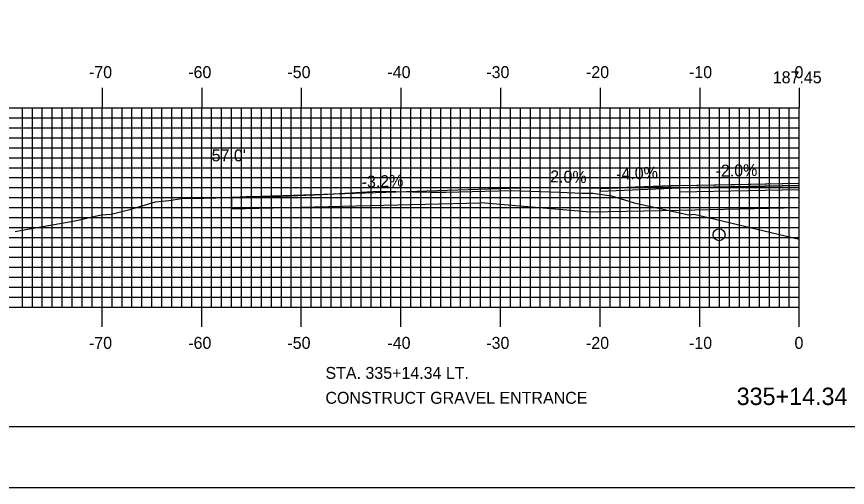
# Model space of a CAD drawing. Extents: x 1823573 to 1823916, y 442591 to 442811.
# Drawn here: x 1823659.7 to 1823743.1, y 442590.5 to 442637.8 of the extents above; entities that cross this region are included whole.
import ezdxf

# ---------------------------------------------------------------- set-up
doc = ezdxf.new("R2010")
doc.units = 0
for name, color, linetype in [('ANNOTATION', 7, 'Continuous'), ('BORDER', 7, 'Continuous'), ('D_Roadway_Centerline', 7, 'Continuous'), ('D_Roadway_Centerline_Text', 7, 'Continuous'), ('D_Roadway_Edge_Shoulder', 7, 'Continuous'), ('D_Roadway_Edge_TW', 7, 'Continuous'), ('D_Roadway_Pavement', 7, 'Continuous'), ('D_Roadway_SubGrade', 7, 'Continuous'), ('D_Text_Standard', 7, 'Continuous'), ('H_V ANNOTATION', 7, 'Continuous'), ('MAJOR', 7, 'Continuous'), ('MINOR', 7, 'Continuous'), ('PLOT BOUNDARY', 7, 'Continuous'), ('S_Drainage_Invert', 7, 'Continuous'), ('S_Roadway_Centerline', 7, 'Continuous')]:
    doc.layers.add(name, color=color, linetype=linetype)

msp = doc.modelspace()

# ---------------------------------------------------------------- linework, layer by layer
at = {"layer": 'BORDER'}
msp.add_lwpolyline([(1823588.709, 442596.665), (1823908.709, 442596.665), (1823908.709, 442806.665), (1823588.709, 442806.665)], close=True, dxfattribs=at)
at = {"layer": 'D_Roadway_Centerline'}
for p, q in [((1823681.309, 442619.681), (1823681.309, 442618.514)), ((1823681.309, 442618.514), (1823706.325, 442619.123))]:
    msp.add_line(p, q, dxfattribs=at)
for points in [[(1823718.309, 442620.556), (1823712.309, 442620.676), (1823681.309, 442619.681)], [(1823718.309, 442620.556), (1823721.974, 442620.703), (1823726.309, 442620.876), (1823731.806, 442620.986), (1823738.309, 442621.116)], [(1823718.325, 442618.216), (1823717.325, 442618.196), (1823706.325, 442619.123)]]:
    msp.add_lwpolyline(points, dxfattribs=at)
at = {"layer": 'D_Roadway_Edge_Shoulder'}
msp.add_lwpolyline([(1823726.309, 442620.876), (1823718.309, 442620.556), (1823718.309, 442620.306), (1823726.309, 442620.626)], close=True, dxfattribs=at)
at = {"layer": 'D_Roadway_Edge_TW'}
msp.add_lwpolyline([(1823738.309, 442620.866), (1823726.309, 442620.626), (1823726.309, 442620.876), (1823738.309, 442621.116)], dxfattribs=at)
at = {"layer": 'D_Roadway_Pavement'}
msp.add_lwpolyline([(1823738.309, 442620.449), (1823726.309, 442620.209), (1823726.309, 442620.626), (1823738.309, 442620.866)], dxfattribs=at)
at = {"layer": 'D_Roadway_SubGrade'}
for points in [[(1823718.309, 442620.556), (1823718.309, 442620.306), (1823726.309, 442620.626), (1823738.309, 442620.866)], [(1823738.309, 442618.616), (1823726.309, 442618.376), (1823717.325, 442618.196)]]:
    msp.add_lwpolyline(points, dxfattribs=at)
at = {"layer": 'MAJOR'}
for p, q in [((1823668.309, 442630.669), (1823668.309, 442628.665)), ((1823678.309, 442630.669), (1823678.309, 442628.665)), ((1823688.309, 442630.669), (1823688.309, 442628.665)), ((1823698.309, 442630.669), (1823698.309, 442628.665)), ((1823708.309, 442630.669), (1823708.309, 442628.665)), ((1823718.309, 442630.669), (1823718.309, 442628.665)), ((1823728.309, 442630.669), (1823728.309, 442628.665)), ((1823738.309, 442630.669), (1823738.309, 442628.665)), ((1823598.309, 442628.665), (1823738.309, 442628.665)), ((1823598.309, 442628.665), (1823738.309, 442628.665)), ((1823668.309, 442608.665), (1823668.309, 442628.665)), ((1823678.309, 442608.665), (1823678.309, 442628.665)), ((1823688.309, 442608.665), (1823688.309, 442628.665)), ((1823698.309, 442608.665), (1823698.309, 442628.665)), ((1823708.309, 442608.665), (1823708.309, 442628.665)), ((1823718.309, 442608.665), (1823718.309, 442628.665)), ((1823728.309, 442608.665), (1823728.309, 442628.665)), ((1823738.309, 442608.665), (1823738.309, 442628.665)), ((1823598.309, 442623.665), (1823738.309, 442623.665)), ((1823598.309, 442618.665), (1823738.309, 442618.665)), ((1823598.309, 442613.665), (1823738.309, 442613.665)), ((1823598.309, 442608.665), (1823738.309, 442608.665)), ((1823598.309, 442608.665), (1823738.309, 442608.665)), ((1823668.309, 442606.661), (1823668.309, 442608.665)), ((1823678.309, 442606.661), (1823678.309, 442608.665)), ((1823688.309, 442606.661), (1823688.309, 442608.665)), ((1823698.309, 442606.661), (1823698.309, 442608.665)), ((1823708.309, 442606.661), (1823708.309, 442608.665)), ((1823718.309, 442606.661), (1823718.309, 442608.665)), ((1823728.309, 442606.661), (1823728.309, 442608.665)), ((1823738.309, 442606.661), (1823738.309, 442608.665))]:
    msp.add_line(p, q, dxfattribs=at)
at = {"layer": 'MINOR'}
for p, q in [((1823660.309, 442608.665), (1823660.309, 442628.665)), ((1823661.309, 442608.665), (1823661.309, 442628.665)), ((1823662.309, 442608.665), (1823662.309, 442628.665)), ((1823663.309, 442608.665), (1823663.309, 442628.665)), ((1823664.309, 442608.665), (1823664.309, 442628.665)), ((1823665.309, 442608.665), (1823665.309, 442628.665)), ((1823666.309, 442608.665), (1823666.309, 442628.665)), ((1823667.309, 442608.665), (1823667.309, 442628.665)), ((1823669.309, 442608.665), (1823669.309, 442628.665)), ((1823670.309, 442608.665), (1823670.309, 442628.665)), ((1823671.309, 442608.665), (1823671.309, 442628.665)), ((1823672.309, 442608.665), (1823672.309, 442628.665)), ((1823673.309, 442608.665), (1823673.309, 442628.665)), ((1823674.309, 442608.665), (1823674.309, 442628.665)), ((1823675.309, 442608.665), (1823675.309, 442628.665)), ((1823676.309, 442608.665), (1823676.309, 442628.665)), ((1823677.309, 442608.665), (1823677.309, 442628.665)), ((1823679.309, 442608.665), (1823679.309, 442628.665)), ((1823680.309, 442608.665), (1823680.309, 442628.665)), ((1823681.309, 442608.665), (1823681.309, 442628.665)), ((1823682.309, 442608.665), (1823682.309, 442628.665)), ((1823683.309, 442608.665), (1823683.309, 442628.665)), ((1823684.309, 442608.665), (1823684.309, 442628.665)), ((1823685.309, 442608.665), (1823685.309, 442628.665)), ((1823686.309, 442608.665), (1823686.309, 442628.665)), ((1823687.309, 442608.665), (1823687.309, 442628.665)), ((1823689.309, 442608.665), (1823689.309, 442628.665)), ((1823690.309, 442608.665), (1823690.309, 442628.665)), ((1823691.309, 442608.665), (1823691.309, 442628.665)), ((1823692.309, 442608.665), (1823692.309, 442628.665)), ((1823693.309, 442608.665), (1823693.309, 442628.665)), ((1823694.309, 442608.665), (1823694.309, 442628.665)), ((1823695.309, 442608.665), (1823695.309, 442628.665)), ((1823696.309, 442608.665), (1823696.309, 442628.665)), ((1823697.309, 442608.665), (1823697.309, 442628.665)), ((1823699.309, 442608.665), (1823699.309, 442628.665)), ((1823700.309, 442608.665), (1823700.309, 442628.665)), ((1823701.309, 442608.665), (1823701.309, 442628.665)), ((1823702.309, 442608.665), (1823702.309, 442628.665)), ((1823703.309, 442608.665), (1823703.309, 442628.665)), ((1823704.309, 442608.665), (1823704.309, 442628.665)), ((1823705.309, 442608.665), (1823705.309, 442628.665)), ((1823706.309, 442608.665), (1823706.309, 442628.665)), ((1823707.309, 442608.665), (1823707.309, 442628.665)), ((1823709.309, 442608.665), (1823709.309, 442628.665)), ((1823710.309, 442608.665), (1823710.309, 442628.665)), ((1823711.309, 442608.665), (1823711.309, 442628.665)), ((1823712.309, 442608.665), (1823712.309, 442628.665)), ((1823713.309, 442608.665), (1823713.309, 442628.665)), ((1823714.309, 442608.665), (1823714.309, 442628.665)), ((1823715.309, 442608.665), (1823715.309, 442628.665)), ((1823716.309, 442608.665), (1823716.309, 442628.665)), ((1823717.309, 442608.665), (1823717.309, 442628.665)), ((1823719.309, 442608.665), (1823719.309, 442628.665)), ((1823720.309, 442608.665), (1823720.309, 442628.665)), ((1823721.309, 442608.665), (1823721.309, 442628.665)), ((1823722.309, 442608.665), (1823722.309, 442628.665)), ((1823723.309, 442608.665), (1823723.309, 442628.665)), ((1823724.309, 442608.665), (1823724.309, 442628.665)), ((1823725.309, 442608.665), (1823725.309, 442628.665)), ((1823726.309, 442608.665), (1823726.309, 442628.665)), ((1823727.309, 442608.665), (1823727.309, 442628.665)), ((1823729.309, 442608.665), (1823729.309, 442628.665)), ((1823730.309, 442608.665), (1823730.309, 442628.665)), ((1823731.309, 442608.665), (1823731.309, 442628.665)), ((1823732.309, 442608.665), (1823732.309, 442628.665)), ((1823733.309, 442608.665), (1823733.309, 442628.665)), ((1823734.309, 442608.665), (1823734.309, 442628.665)), ((1823735.309, 442608.665), (1823735.309, 442628.665)), ((1823736.309, 442608.665), (1823736.309, 442628.665)), ((1823737.309, 442608.665), (1823737.309, 442628.665)), ((1823598.309, 442627.665), (1823738.309, 442627.665)), ((1823598.309, 442626.665), (1823738.309, 442626.665)), ((1823598.309, 442625.665), (1823738.309, 442625.665)), ((1823598.309, 442624.665), (1823738.309, 442624.665)), ((1823598.309, 442622.665), (1823738.309, 442622.665)), ((1823598.309, 442621.665), (1823738.309, 442621.665)), ((1823598.309, 442620.665), (1823738.309, 442620.665)), ((1823598.309, 442619.665), (1823738.309, 442619.665)), ((1823598.309, 442617.665), (1823738.309, 442617.665)), ((1823598.309, 442616.665), (1823738.309, 442616.665)), ((1823598.309, 442615.665), (1823738.309, 442615.665)), ((1823598.309, 442614.665), (1823738.309, 442614.665)), ((1823598.309, 442612.665), (1823738.309, 442612.665)), ((1823598.309, 442611.665), (1823738.309, 442611.665)), ((1823598.309, 442610.665), (1823738.309, 442610.665)), ((1823598.309, 442609.665), (1823738.309, 442609.665))]:
    msp.add_line(p, q, dxfattribs=at)
at = {"layer": 'PLOT BOUNDARY'}
msp.add_lwpolyline([(1823572.522, 442590.547), (1823912.522, 442590.547), (1823912.522, 442810.547), (1823572.522, 442810.547)], close=True, dxfattribs=at)
at = {"layer": 'S_Drainage_Invert'}
msp.add_circle((1823730.252, 442615.927), 0.6, dxfattribs=at)
at = {"layer": 'S_Roadway_Centerline'}
msp.add_lwpolyline([(1823659.583, 442616.261), (1823660.287, 442616.401), (1823665.589, 442617.335), (1823668.214, 442617.92), (1823669.21, 442617.983), (1823671.111, 442618.449), (1823673.687, 442619.241), (1823675.014, 442619.368), (1823676.306, 442619.578), (1823678.51, 442619.587), (1823680.942, 442619.657), (1823683.391, 442619.815), (1823685.52, 442619.784), (1823690.39, 442619.984), (1823696.048, 442620.316), (1823701.253, 442620.201), (1823702.806, 442620.214), (1823709.432, 442620.384), (1823714.268, 442620.208), (1823716.518, 442620.117), (1823716.724, 442620.119), (1823716.904, 442620.094), (1823717.596, 442620.095), (1823719.468, 442619.833), (1823721.722, 442619.122), (1823727.219, 442617.922), (1823727.75, 442617.983), (1823736.18, 442615.979), (1823738.309, 442615.479)], dxfattribs=at)

# ---------------------------------------------------------------- texts
at = {"layer": 'ANNOTATION'}
for s, rotation, p in [('2.0%', 358.85424, (1823713.286, 442621.191)), ('-4.0%', 2.29061, (1823719.94, 442621.423)), ('-2.0%', 1.14576, (1823729.915, 442621.749)), ('-3.2%', 1.83952, (1823694.385, 442620.635))]:
    msp.add_text(s, height=1.2, rotation=rotation, dxfattribs=at).set_placement(p)
at = {"layer": 'D_Roadway_Centerline'}
for s, p in [('C', (1823738.303, 442621.116)), ('L', (1823738.309, 442621.109))]:
    msp.add_text(s, height=0.0146, dxfattribs=at).set_placement(p)
at = {"layer": 'D_Roadway_Centerline_Text'}
msp.add_text('187.45', height=1.2, dxfattribs=at).set_placement((1823735.649, 442631.146))
at = {"layer": 'D_Text_Standard'}
for s, p in [("57.0'", (1823679.313, 442623.3)), ('STA. 335+14.34 LT.', (1823690.737, 442601.446)), ('CONSTRUCT GRAVEL ENTRANCE', (1823690.737, 442598.946))]:
    msp.add_text(s, height=1.2, dxfattribs=at).set_placement(p)
at = {"layer": 'H_V ANNOTATION'}
for s, height, p in [('-70', 1.2, (1823666.992, 442631.665)), ('-60', 1.2, (1823676.96, 442631.665)), ('-50', 1.2, (1823686.917, 442631.665)), ('-40', 1.2, (1823696.96, 442631.665)), ('-30', 1.2, (1823706.885, 442631.665)), ('-20', 1.2, (1823716.896, 442631.665)), ('-10', 1.2, (1823727.238, 442631.665)), ('0', 1.2, (1823737.827, 442631.665)), ('-70', 1.2, (1823666.992, 442604.465)), ('-60', 1.2, (1823676.96, 442604.465)), ('-50', 1.2, (1823686.917, 442604.465)), ('-40', 1.2, (1823696.96, 442604.465)), ('-30', 1.2, (1823706.885, 442604.465)), ('-20', 1.2, (1823716.896, 442604.465)), ('-10', 1.2, (1823727.238, 442604.465)), ('0', 1.2, (1823737.827, 442604.465)), ('335+14.34', 1.75, (1823732.02, 442598.821))]:
    msp.add_text(s, height=height, dxfattribs=at).set_placement(p)
at = {"layer": 'S_Roadway_Centerline'}
for s, p in [('C', (1823696.043, 442620.316)), ('C', (1823696.043, 442620.316)), ('L', (1823696.048, 442620.309)), ('L', (1823696.048, 442620.309))]:
    msp.add_text(s, height=0.0146, dxfattribs=at).set_placement(p)

doc.saveas('drawing.dxf')
